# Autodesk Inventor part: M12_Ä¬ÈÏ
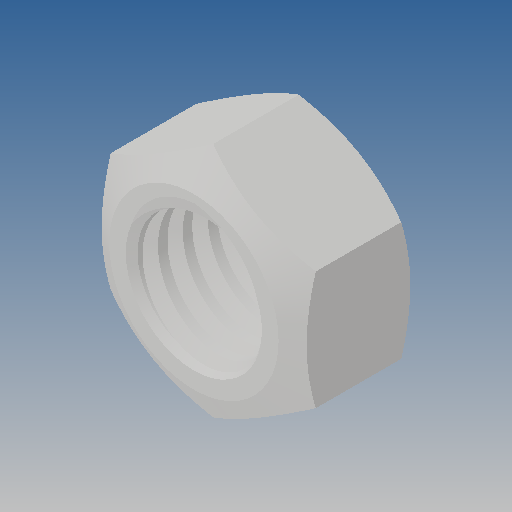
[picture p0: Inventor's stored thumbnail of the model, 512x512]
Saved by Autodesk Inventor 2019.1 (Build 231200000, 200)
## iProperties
Created: 2010-06
Part Number: M12_Ä¬ÈÏ
Material: Ogólny
Document SubType Name: Modeling
Designer: CADENGINEERING4
Density: 1 g/cm^3
Appearance: Domyślna
Author: CADENGINEERING4
Revision Number: ÈÎºÎ
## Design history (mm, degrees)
feature "NONE"
node "Bryła1"
